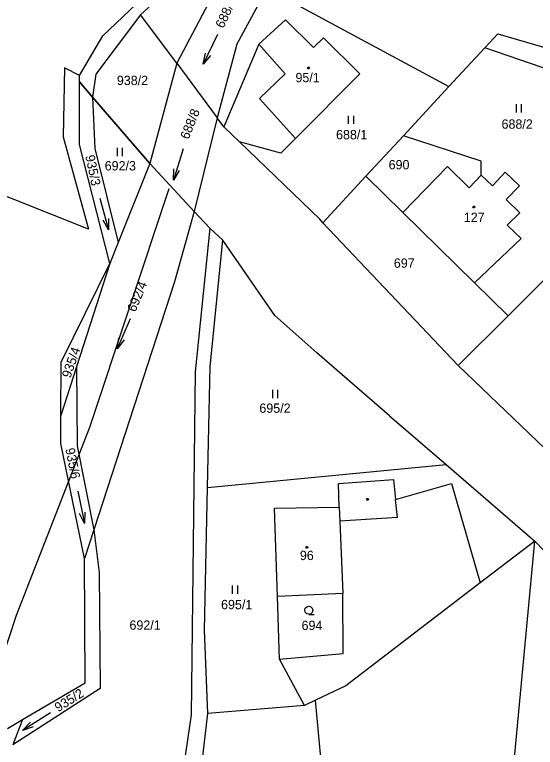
# Model space of a CAD drawing. Extents: x -580551 to -575069, y -1073031 to -1067931.
# Drawn here: x -578567 to -578472.1, y -1070971.8 to -1070838.3 of the extents above; entities that cross this region are included whole.
import ezdxf

# ---------------------------------------------------------------- set-up
doc = ezdxf.new("R2010")
doc.units = 0
for name, color, linetype in [('Druh pozemku', 7, 'Continuous'), ('Hranice státní', 7, 'Continuous'), ('Hranice z rastru', 7, 'Continuous'), ('Katastrální hranice', 7, 'Continuous'), ('Parcela', 7, 'Continuous'), ('Parcelní číslo', 7, 'Continuous'), ('Parcelní číslo_stavba', 7, 'Continuous'), ('SR - hranice státu', 7, 'Continuous'), ('Vnitřní kresba', 7, 'Continuous'), ('Vrstva 6', 7, 'Continuous')]:
    doc.layers.add(name, color=color, linetype=linetype)

msp = doc.modelspace()

# ---------------------------------------------------------------- linework, layer by layer
at = {"layer": 'Druh pozemku'}
for p, q in [((-578530.026, -1070841.893), (-578532.654, -1070847.287)), ((-578475.65, -1070854.58), (-578475.65, -1070856.08)), ((-578474.65, -1070856.08), (-578474.65, -1070854.58)), ((-578506.22, -1070856.67), (-578506.22, -1070858.17)), ((-578505.22, -1070858.17), (-578505.22, -1070856.67)), ((-578548.34, -1070862.53), (-578548.34, -1070864.03)), ((-578547.34, -1070864.03), (-578547.34, -1070862.53)), ((-578536.319, -1070862.715), (-578538.101, -1070868.445)), ((-578551.483, -1070871.707), (-578549.897, -1070877.493)), ((-578545.991, -1070893.687), (-578548.329, -1070899.213)), ((-578520.06, -1070906.66), (-578520.06, -1070908.16)), ((-578519.06, -1070908.16), (-578519.06, -1070906.66)), ((-578555.495, -1070925.16), (-578554.305, -1070931.04)), ((-578527.37, -1070942.36), (-578527.37, -1070943.86)), ((-578526.37, -1070943.86), (-578526.37, -1070942.36)), ((-578560.499, -1070965.565), (-578565.581, -1070968.755))]:
    msp.add_line(p, q, dxfattribs=at)
for points in [[(-578531.329, -1070845.708), (-578532.654, -1070847.287), (-578532.227, -1070845.27)], [(-578537.029, -1070866.683), (-578538.101, -1070868.445), (-578537.984, -1070866.387)], [(-578549.943, -1070875.432), (-578549.897, -1070877.493), (-578550.908, -1070875.697)], [(-578547.089, -1070897.566), (-578548.329, -1070899.213), (-578548.01, -1070897.176)], [(-578554.212, -1070928.981), (-578554.305, -1070931.04), (-578555.192, -1070929.179)], [(-578513.41, -1070947.59), (-578513.79, -1070947.49), (-578514.06, -1070947.22), (-578514.16, -1070946.85), (-578514.06, -1070946.48), (-578513.79, -1070946.21), (-578513.42, -1070946.11), (-578513.05, -1070946.21), (-578512.78, -1070946.48), (-578512.68, -1070946.86), (-578512.78, -1070947.24), (-578513.05, -1070947.51), (-578513.43, -1070947.61), (-578512.43, -1070947.61)], [(-578563.621, -1070968.115), (-578565.581, -1070968.755), (-578564.153, -1070967.268)]]:
    msp.add_lwpolyline(points, dxfattribs=at)
for points in [[(-578513.41, -1070847.84), (-578513.32, -1070847.99), (-578513.41, -1070848.14), (-578513.59, -1070848.14), (-578513.68, -1070847.99), (-578513.59, -1070847.84)], [(-578483.24, -1070873.16), (-578483.15, -1070873.31), (-578483.24, -1070873.46), (-578483.42, -1070873.46), (-578483.51, -1070873.31), (-578483.42, -1070873.16)], [(-578502.62, -1070926.48), (-578502.53, -1070926.63), (-578502.62, -1070926.78), (-578502.8, -1070926.78), (-578502.89, -1070926.63), (-578502.8, -1070926.48)], [(-578513.67, -1070935.22), (-578513.58, -1070935.37), (-578513.67, -1070935.52), (-578513.85, -1070935.52), (-578513.94, -1070935.37), (-578513.85, -1070935.22)]]:
    msp.add_lwpolyline(points, close=True, dxfattribs=at)
at = {"layer": 'Hranice státní'}
msp.add_lwpolyline([(-578555.22, -1070850.52), (-578555.22, -1070849.34), (-578557.91, -1070847.93), (-578558.16, -1070860.5), (-578553.56, -1070877.35), (-578573.61, -1070869.38), (-578576.59, -1070868.2), (-578595.84, -1070860.55), (-578614.36, -1070881.73)], dxfattribs=at)
at = {"layer": 'Hranice z rastru'}
for points in [[(-578538.941, -1070870.027), (-578553.355, -1070913.557), (-578566.72, -1070947.779)], [(-578566.72, -1070947.779), (-578583.48, -1070998.532), (-578590.876, -1071020.93), (-578592.521, -1071043.374), (-578590.032, -1071060.419), (-578576.797, -1071098.705), (-578560.811, -1071139.089), (-578544.825, -1071179.473), (-578532.639, -1071204.254), (-578528.184, -1071216.579), (-578534.736, -1071226.806), (-578537.749, -1071239.524), (-578532.246, -1071274.139), (-578521.632, -1071309.672), (-578516.391, -1071321.603), (-578520.977, -1071339.96), (-578529.232, -1071361.069)]]:
    msp.add_lwpolyline(points, dxfattribs=at)
at = {"layer": 'Katastrální hranice'}
for p, q in [((-578550.94, -1070842.11), (-578533.21, -1070825.15)), ((-578555.22, -1070849.34), (-578550.94, -1070842.11)), ((-578555.22, -1070850.52), (-578555.22, -1070849.34)), ((-578555.23, -1070861.93), (-578555.22, -1070850.52)), ((-578549.65, -1070883.65), (-578555.23, -1070861.93)), ((-578558.57, -1070901.61), (-578549.65, -1070883.65)), ((-578558.61, -1070911.35), (-578558.57, -1070901.61)), ((-578558.63, -1070916.44), (-578558.61, -1070911.35)), ((-578554.29, -1070937.43), (-578558.63, -1070916.44)), ((-578554.15, -1070960.09), (-578554.29, -1070937.43)), ((-578565.57, -1070966.76), (-578554.15, -1070960.09)), ((-578568.35, -1070968.39), (-578565.57, -1070966.76))]:
    msp.add_line(p, q, dxfattribs=at)
at = {"layer": 'Parcela'}
for p, q in [((-578544.11, -1070838.27), (-578531.87, -1070827.12)), ((-578528.13, -1070829.32), (-578537.45, -1070847.09)), ((-578521.03, -1070833.49), (-578526.55, -1070843.66)), ((-578521.03, -1070833.49), (-578487.87, -1070851.36)), ((-578544.11, -1070838.27), (-578552.21, -1070849.11)), ((-578537.45, -1070847.09), (-578544.11, -1070838.27)), ((-578517.64, -1070839.17), (-578522.53, -1070843.62)), ((-578512.56, -1070844.25), (-578517.64, -1070839.17)), ((-578481.33, -1070844.29), (-578478.99, -1070841.75)), ((-578478.99, -1070841.75), (-578462.56, -1070846.53)), ((-578510.76, -1070842.45), (-578512.56, -1070844.25)), ((-578504.14, -1070849.07), (-578510.76, -1070842.45)), ((-578526.55, -1070843.66), (-578530.09, -1070857.05)), ((-578522.53, -1070843.62), (-578528.88, -1070858.69)), ((-578487.87, -1070851.36), (-578481.33, -1070844.29)), ((-578465.05, -1070849.94), (-578481.33, -1070844.29)), ((-578537.45, -1070847.09), (-578542.41, -1070865.4)), ((-578552.21, -1070849.11), (-578552.84, -1070853.28)), ((-578504.14, -1070849.07), (-578515.87, -1070860.81)), ((-578552.84, -1070853.28), (-578555.22, -1070850.52)), ((-578487.87, -1070851.36), (-578496.17, -1070860.34)), ((-578542.41, -1070865.4), (-578552.84, -1070853.28)), ((-578552.84, -1070853.28), (-578552.4, -1070862.66)), ((-578530.09, -1070857.05), (-578534.28, -1070874.14)), ((-578528.88, -1070858.69), (-578530.09, -1070857.05)), ((-578526.06, -1070861.42), (-578528.88, -1070858.69)), ((-578515.87, -1070860.81), (-578518.54, -1070863.48)), ((-578496.17, -1070860.34), (-578503.01, -1070867.73)), ((-578481.99, -1070864.98), (-578496.17, -1070860.34)), ((-578518.54, -1070863.48), (-578526.06, -1070861.42)), ((-578511.43, -1070875.54), (-578526.06, -1070861.42)), ((-578552.4, -1070862.66), (-578548.13, -1070879.81)), ((-578542.41, -1070865.4), (-578548.13, -1070879.81)), ((-578534.28, -1070874.14), (-578542.41, -1070865.4)), ((-578488.15, -1070865.94), (-578496.26, -1070874.35)), ((-578484.21, -1070869.82), (-578488.15, -1070865.94)), ((-578481.98, -1070867.53), (-578481.99, -1070864.98)), ((-578481.98, -1070867.53), (-578484.21, -1070869.82)), ((-578479.95, -1070869.48), (-578481.98, -1070867.53)), ((-578477.61, -1070867), (-578479.95, -1070869.48)), ((-578475.05, -1070869.49), (-578477.61, -1070867)), ((-578503.01, -1070867.73), (-578510.87, -1070876.24)), ((-578496.26, -1070874.35), (-578503.01, -1070867.73)), ((-578477.45, -1070871.94), (-578475.05, -1070869.49)), ((-578474.95, -1070874.37), (-578477.45, -1070871.94)), ((-578534.28, -1070874.14), (-578537.91, -1070886.97)), ((-578531.45, -1070877.21), (-578534.28, -1070874.14)), ((-578510.87, -1070876.24), (-578511.43, -1070875.54)), ((-578483.2, -1070887.16), (-578496.26, -1070874.35)), ((-578477.24, -1070876.64), (-578474.95, -1070874.37)), ((-578510.87, -1070876.24), (-578486.19, -1070902.23)), ((-578474.74, -1070879.09), (-578477.24, -1070876.64)), ((-578531.45, -1070877.21), (-578534.14, -1070903.36)), ((-578529.09, -1070879.36), (-578531.45, -1070877.21)), ((-578531.39, -1070902.41), (-578529.09, -1070879.36)), ((-578519.58, -1070893.11), (-578529.09, -1070879.36)), ((-578483.2, -1070887.16), (-578474.74, -1070879.09)), ((-578548.13, -1070879.81), (-578549.65, -1070883.65)), ((-578477.11, -1070893.14), (-578464.15, -1070880.16)), ((-578549.65, -1070883.65), (-578555.74, -1070902.46)), ((-578537.91, -1070886.97), (-578552.57, -1070932.2)), ((-578477.11, -1070893.14), (-578483.2, -1070887.16)), ((-578511.94, -1070899.89), (-578519.58, -1070893.11)), ((-578486.19, -1070902.23), (-578477.11, -1070893.14)), ((-578504.2, -1070906.66), (-578511.94, -1070899.89)), ((-578458.78, -1070928.52), (-578486.19, -1070902.23)), ((-578555.74, -1070902.46), (-578558.61, -1070911.35)), ((-578555.74, -1070902.46), (-578555.63, -1070916.86)), ((-578534.14, -1070903.36), (-578534.88, -1070965.92)), ((-578531.87, -1070924.46), (-578531.39, -1070902.41)), ((-578498.71, -1070911.37), (-578504.2, -1070906.66)), ((-578498.71, -1070911.37), (-578488.36, -1070920.3)), ((-578555.63, -1070916.86), (-578552.57, -1070932.2)), ((-578531.87, -1070924.46), (-578488.36, -1070920.3)), ((-578488.36, -1070920.3), (-578472.22, -1070934.24)), ((-578507.99, -1070923.73), (-578497.99, -1070923)), ((-578497.99, -1070923), (-578497.61, -1070926.64)), ((-578532.44, -1070950.5), (-578531.87, -1070924.46)), ((-578507.9, -1070928.08), (-578507.99, -1070923.73)), ((-578497.61, -1070926.64), (-578487.42, -1070923.76)), ((-578487.42, -1070923.76), (-578482.2, -1070941.87)), ((-578519.66, -1070928.24), (-578507.9, -1070928.08)), ((-578519.15, -1070944.32), (-578519.66, -1070928.24)), ((-578552.57, -1070932.2), (-578554.29, -1070937.43)), ((-578552.57, -1070932.2), (-578551.6, -1070939.98)), ((-578472.22, -1070934.24), (-578482.2, -1070941.87)), ((-578476.22, -1070976.47), (-578472.22, -1070934.24)), ((-578472.22, -1070934.24), (-578453.14, -1070954.39)), ((-578551.6, -1070939.98), (-578551.41, -1070961.1)), ((-578482.2, -1070941.87), (-578506.68, -1070960.6)), ((-578507.21, -1070943.78), (-578519.15, -1070944.32)), ((-578518.78, -1070955.76), (-578519.15, -1070944.32)), ((-578507.18, -1070954.75), (-578507.21, -1070943.78)), ((-578531.83, -1070965.69), (-578532.44, -1070950.5)), ((-578518.78, -1070955.76), (-578507.18, -1070954.75)), ((-578514.23, -1070964.19), (-578518.78, -1070955.76)), ((-578551.41, -1070961.1), (-578567.34, -1070971.37)), ((-578506.68, -1070960.6), (-578512.2, -1070963.23)), ((-578512.2, -1070963.23), (-578514.23, -1070964.19)), ((-578508.85, -1070999.6), (-578512.2, -1070963.23)), ((-578514.23, -1070964.19), (-578531.83, -1070965.69)), ((-578534.88, -1070965.92), (-578537.36, -1070983.5)), ((-578535.31, -1070996.1), (-578531.83, -1070965.69)), ((-578565.57, -1070966.76), (-578567.34, -1070971.37))]:
    msp.add_line(p, q, dxfattribs=at)
at = {"layer": 'SR - hranice státu'}
for points in [[(-578555.22, -1070850.52), (-578552.84, -1070853.28), (-578542.41, -1070865.4), (-578534.28, -1070874.14), (-578537.91, -1070886.97), (-578552.57, -1070932.2)], [(-578552.57, -1070932.2), (-578551.6, -1070939.98), (-578551.41, -1070961.1), (-578567.34, -1070971.37)]]:
    msp.add_lwpolyline(points, dxfattribs=at)
at = {"layer": 'Vnitřní kresba'}
for p, q in [((-578522.53, -1070843.62), (-578517.75, -1070849.05)), ((-578517.75, -1070849.05), (-578522.42, -1070853.53)), ((-578522.42, -1070853.53), (-578515.87, -1070860.81)), ((-578497.26, -1070929.93), (-578497.61, -1070926.64)), ((-578507.9, -1070928.08), (-578507.79, -1070930.63)), ((-578497.26, -1070929.93), (-578507.79, -1070930.63)), ((-578507.79, -1070930.63), (-578507.21, -1070943.78))]:
    msp.add_line(p, q, dxfattribs=at)
at = {"layer": 'Vrstva 6'}
msp.add_line((-578537.45, -1070847.09), (-578530.09, -1070857.05), dxfattribs=at)

# ---------------------------------------------------------------- texts
at = {"layer": 'Parcelní číslo'}
for s, rotation, p in [('688/7', 65.37448, (-578528.977, -1070840.854)), ('688/8', 68.23927, (-578535.337, -1070861.124)), ('935/3', 281.78064, (-578554.158, -1070864.014)), ('692/4', 67.49443, (-578545.014, -1070892.589)), ('935/4', 70.93218, (-578556.868, -1070904.625)), ('935/6', 280.92121, (-578557.786, -1070917.42)), ('935/2', 32.02834, (-578559.073, -1070965.464))]:
    msp.add_text(s, height=1.7, rotation=rotation, dxfattribs=at).set_placement(p)
for s, p in [('938/2', (-578548.395, -1070851.09)), ('688/2', (-578478.291, -1070859.05)), ('688/1', (-578508.449, -1070860.98)), ('692/3', (-578550.611, -1070866.66)), ('690', (-578498.868, -1070866.46)), ('697', (-578497.919, -1070884.4)), ('695/2', (-578522.426, -1070910.85)), ('695/1', (-578529.404, -1070946.66)), ('692/1', (-578546.097, -1070950.4)), ('694', (-578514.734, -1070950.46))]:
    msp.add_text(s, height=1.7, dxfattribs=at).set_placement(p)
at = {"layer": 'Parcelní číslo_stavba'}
for s, p in [('95/1', (-578515.845, -1070850.57)), ('127', (-578485.167, -1070876.05)), ('96', (-578515.046, -1070937.7))]:
    msp.add_text(s, height=1.7, dxfattribs=at).set_placement(p)

doc.saveas('drawing.dxf')
